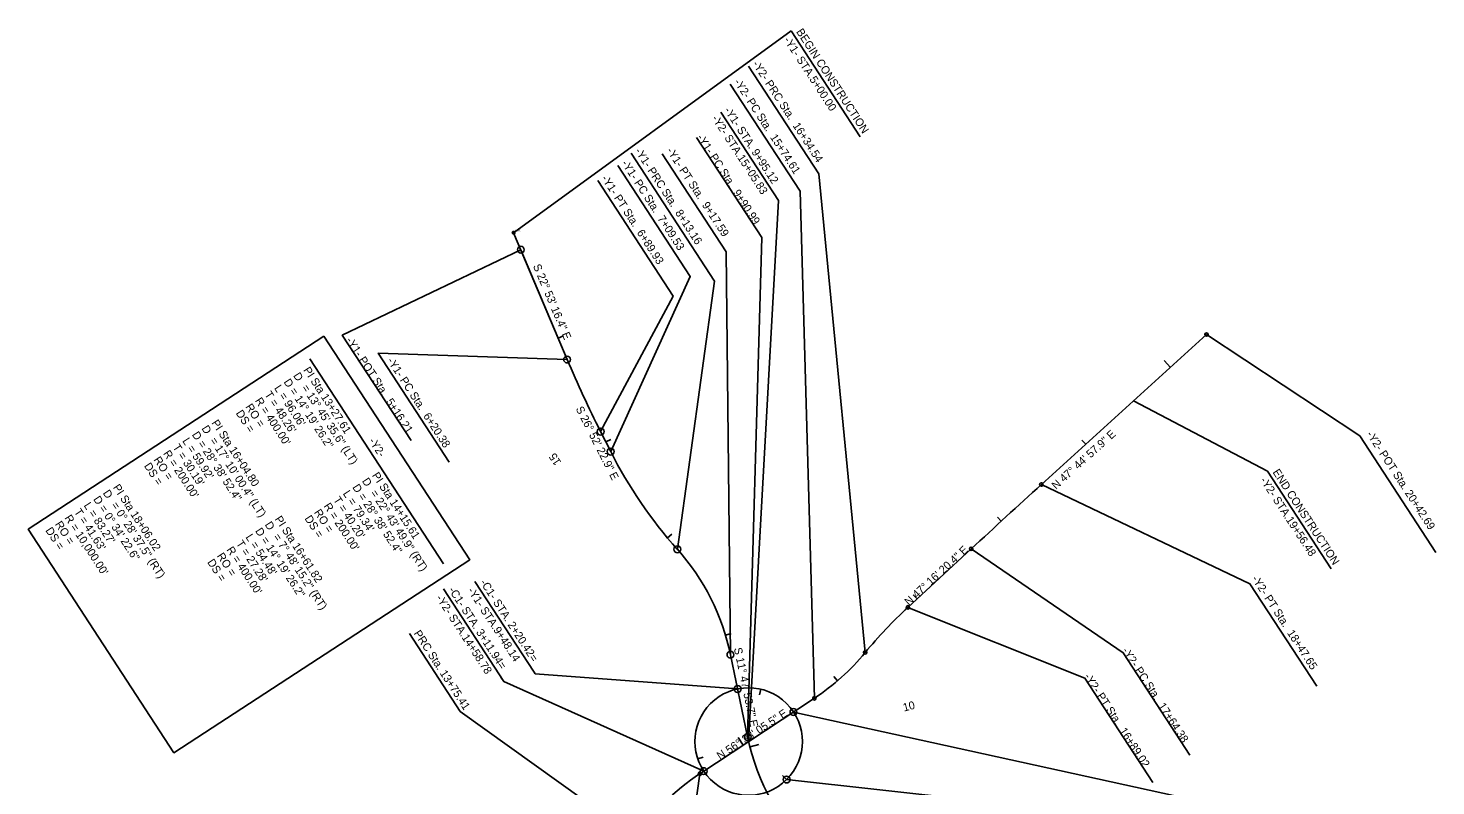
# Model space of a CAD drawing. Extents: x 1636713 to 1642783, y 841520 to 844371.
# Drawn here: x 1639748 to 1640979, y 843708 to 844371 of the extents above; entities that cross this region are included whole.
import ezdxf

# ---------------------------------------------------------------- set-up
doc = ezdxf.new("R2010")
doc.units = 0
for name, color, linetype in [('COGO Default Chain', 7, 'Continuous'), ('Cogo Default Point CELL', 7, 'Continuous'), ('COGO Default Point Number', 7, 'Continuous'), ('Prop Horizontal Alignment', 7, 'Continuous'), ('Prop Horizontal Alignment Curve and Spiral Data', 7, 'Continuous'), ('Prop Horizontal Alignment Direction Label', 7, 'Continuous'), ('Prop Horizontal Alignment Station Label', 7, 'Continuous'), ('Prop Horizontal Alignment Tick Label', 7, 'Continuous'), ('Prop Horizontal Alignment Tick Large', 7, 'Continuous'), ('Prop Horizontal Alignment Tick Small', 7, 'Continuous')]:
    doc.layers.add(name, color=color, linetype=linetype)

msp = doc.modelspace()

# ---------------------------------------------------------------- linework, layer by layer
at = {"layer": 'COGO Default Chain'}
for p, q in [((1640178.6, 844176.8), (1640219.1, 844080.8)), ((1640248.4, 844017.8), (1640257.2, 844000.3)), ((1640361.9, 843822.7), (1640376.9, 843750.8))]:
    msp.add_line(p, q, dxfattribs=at)
for centre, radius, start, end in [((1641140.4, 844469.8), 1000, 202.8879, 206.873), ((1640614, 844181.1), 400, 206.873, 221.7163), ((1640166.2, 843781.8), 200, 11.7982, 41.7163), ((1640572.7, 843791.7), 200, 191.7982, 226.5509)]:
    msp.add_arc(centre, radius, start, end, dxfattribs=at)
at = {"layer": 'Cogo Default Point CELL'}
for points in [[(1640170.8, 844191.7), (1640172.3, 844191.7)], [(1640172.3, 844193.2), (1640172.3, 844191.7)], [(1640172.3, 844191.7), (1640173.8, 844191.7)], [(1640172.3, 844191.7), (1640172.3, 844190.2)]]:
    msp.add_lwpolyline(points, dxfattribs=at)
msp.add_circle((1640172.3, 844191.7), 1.17, dxfattribs=at)
at = {"layer": 'Prop Horizontal Alignment'}
for p, q in [((1640172.3, 844191.7), (1640219.1, 844080.8)), ((1640633.8, 843971.5), (1640778.2, 844102.6)), ((1640248.4, 844017.8), (1640257.2, 844000.3)), ((1640517.1, 843864.1), (1640572.4, 843915.3)), ((1640361.9, 843822.7), (1640376.9, 843750.8)), ((1640335.2, 843718.7), (1640435.3, 843784.6))]:
    msp.add_line(p, q, dxfattribs=at)
for centre, radius, start, end in [((1641140.4, 844469.8), 1000, 202.8879, 206.873), ((1640614, 844181.1), 400, 206.873, 221.7163), ((1647357.6, 836569.4), 10000, 132.25059, 132.72767), ((1640166.2, 843781.8), 200, 11.7982, 41.7163), ((1640788.5, 843570.3), 400, 132.7277, 140.5319), ((1640325.3, 843951.7), 200, 303.3651, 320.5319), ((1640377.8, 843746.8), 47, 45, 135), ((1640377.8, 843746.8), 47, 135, 225), ((1640377.8, 843746.8), 47, 315, 45), ((1640572.7, 843791.7), 200, 191.7982, 226.5509), ((1640445.2, 843551.7), 200, 123.3651, 146.0956), ((1640377.8, 843746.8), 47, 225, 315)]:
    msp.add_arc(centre, radius, start, end, dxfattribs=at)
at = {"layer": 'Prop Horizontal Alignment Curve and Spiral Data'}
msp.add_line((1639994.1, 844081.5), (1640111.1, 843902.1), dxfattribs=at)
msp.add_lwpolyline([(1640006.3, 844101.1), (1640133.9, 843905.7), (1639875.3, 843737), (1639747.8, 843932.4)], close=True, dxfattribs=at)
at = {"layer": 'Prop Horizontal Alignment Station Label'}
for p, q in [((1640475.4, 844275.6), (1640415, 844368.2)), ((1640404, 844219.9), (1640353.5, 844297.2)), ((1640887.3, 843897.7), (1640831.5, 843983.1)), ((1640190.2, 843807.5), (1640138.5, 843886.8)), ((1640163.7, 843799.2), (1640110.9, 843880.3)), ((1640125.5, 843773.2), (1640081.1, 843841.3)), ((1640279.2, 843663.2), (1640125.5, 843773.2))]:
    msp.add_line(p, q, dxfattribs=at)
for points in [[(1640415, 844368.2), (1640172.3, 844191.7)], [(1640377.8, 844337.4), (1640439.3, 844243.2), (1640479.7, 843824.6)], [(1640361.7, 844321.6), (1640422.9, 844227.9), (1640435.3, 843784.6)], [(1640332.3, 844275), (1640389.3, 844187.6), (1640376.9, 843750.8)], [(1640275.1, 844261.2), (1640348.1, 844149.3), (1640315.5, 843914.9)], [(1640361.9, 843822.7), (1640358.1, 844175), (1640302.2, 844260.7)], [(1640263.4, 844250.5), (1640326.8, 844153.4), (1640257.2, 844000.3)], [(1640245.8, 844237.3), (1640311.7, 844136.2), (1640248.4, 844017.8)], [(1640404, 844219.9), (1640377.8, 843746.8)], [(1640082.6, 844010), (1640022.5, 844102.1), (1640178.6, 844176.8)], [(1640978.7, 843912), (1640912.2, 844014), (1640778.2, 844102.6)], [(1640219.1, 844080.8), (1640053.9, 844086.4), (1640116, 843991.2)], [(1640831.5, 843983.1), (1640714.4, 844044.7)], [(1640874.6, 843795.2), (1640816.2, 843884.7), (1640633.8, 843971.5)], [(1640763.7, 843734.9), (1640705.4, 843824.4), (1640572.4, 843915.3)], [(1640731.3, 843710.9), (1640671.9, 843802.1), (1640517.1, 843864.1)], [(1640161.2, 843803.1), (1640163.7, 843799.2), (1640338.5, 843720.9)], [(1640190.2, 843807.5), (1640191.2, 843806.1), (1640368.2, 843792.8)], [(1640761.4, 843696.8), (1640761.4, 843696.9), (1640417, 843772.6)], [(1640339.8, 843246.6), (1640281.4, 843336.1), (1640335.2, 843718.7)], [(1640737.4, 843677.4), (1640411, 843713.6)]]:
    msp.add_lwpolyline(points, dxfattribs=at)
for centre, radius in [((1640178.6, 844176.8), 3), ((1640778.2, 844102.6), 1.5), ((1640219.1, 844080.8), 3), ((1640248.4, 844017.8), 3), ((1640257.2, 844000.3), 3), ((1640633.8, 843971.5), 1.5), ((1640315.5, 843914.9), 3), ((1640572.4, 843915.3), 1.5), ((1640517.1, 843864.1), 1.5), ((1640361.9, 843822.7), 3), ((1640479.7, 843824.6), 1.5), ((1640368.2, 843792.8), 3), ((1640435.3, 843784.6), 1.5), ((1640417, 843772.6), 3), ((1640376.9, 843750.8), 3), ((1640338.5, 843720.9), 3), ((1640335.2, 843718.7), 1.5), ((1640411, 843713.6), 3)]:
    msp.add_circle(centre, radius, dxfattribs=at)
at = {"layer": 'Prop Horizontal Alignment Tick Large'}
for p, q in [((1640746.6, 844073.9), (1640741.2, 844079.9)), ((1640373, 843743.6), (1640368.6, 843750.3)), ((1640379, 843742.1), (1640386.7, 843744.1))]:
    msp.add_line(p, q, dxfattribs=at)
at = {"layer": 'Prop Horizontal Alignment Tick Small'}
for p, q in [((1640211.2, 844099.6), (1640215.8, 844101.6)), ((1640252.9, 844008.8), (1640257.4, 844011)), ((1640672.6, 844006.7), (1640669.2, 844010.4)), ((1640598.6, 843939.4), (1640595.3, 843943.1)), ((1640306.9, 843924.9), (1640310.7, 843928.1)), ((1640525.1, 843871.6), (1640521.7, 843875.2)), ((1640357.6, 843839.7), (1640362.4, 843841.2)), ((1640455.5, 843799.9), (1640452.3, 843803.7)), ((1640388.4, 843792.6), (1640387.3, 843787.7)), ((1640333.3, 843731.6), (1640338, 843733.2)), ((1640411, 843713.6), (1640407.5, 843717.1))]:
    msp.add_line(p, q, dxfattribs=at)

# ---------------------------------------------------------------- texts
at = {"layer": 'COGO Default Point Number'}
msp.add_text('15053', height=1.25, dxfattribs=at).set_placement((1640173.5, 844193))
at = {"layer": 'Prop Horizontal Alignment Curve and Spiral Data'}
for s, p in [('D', (1639979.3, 844066.7)), ('PI Sta 13+27.61', (1639988.1, 844071.6)), ("L = 96.06'", (1639962.6, 844055.8)), ('D = 14%%d 19\' 26.2"', (1639970.9, 844061.2)), ('= 13%%d 45\' 35.6" (LT)', (1639986.6, 844056.1)), ("R = 400.00'", (1639945.8, 844044.8)), ("T = 48.26'", (1639954.2, 844050.3)), ('DS =', (1639929.1, 844033.9)), ('RO = ', (1639937.4, 844039.4)), ('D = 28%%d 38\' 52.4"', (1639890.7, 844015.1)), ('D', (1639899.1, 844020.5)), ('PI Sta 16+04.80', (1639907.8, 844025.4)), ("T = 30.19'", (1639873.9, 844004.2)), ("L = 59.92'", (1639882.3, 844009.6)), ('= 17%%d 10\' 00.4" (LT)', (1639906.3, 844009.9)), ('-Y2-', (1640045.3, 844009.6)), ('RO = ', (1639857.2, 843993.2)), ("R = 200.00'", (1639865.6, 843998.7)), ('DS =', (1639848.8, 843987.8)), ('PI Sta 14+15.61', (1640048.2, 843979.5)), ('PI Sta 18+06.02', (1639821.6, 843969)), ('D = 28%%d 38\' 52.4"', (1640031, 843969.1)), ('D', (1640039.4, 843974.6)), ('D = 0%%d 34\' 22.6"', (1639804.4, 843958.7)), ('D', (1639812.8, 843964.1)), ("T = 40.20'", (1640014.3, 843958.2)), ("L = 79.34'", (1640022.7, 843963.6)), ('= 22%%d 43\' 49.9" (RT)', (1640046.7, 843964)), ("R = 10,000.00'", (1639779.3, 843942.3)), ("T = 41.63'", (1639787.7, 843947.7)), ("L = 83.27'", (1639796.1, 843953.2)), ('= 0%%d 28\' 37.5" (RT)', (1639820.1, 843953.5)), ('PI Sta 16+61.82', (1639963.1, 843941.3)), ('DS =', (1639989.2, 843941.8)), ('RO = ', (1639997.5, 843947.2)), ("R = 200.00'", (1640005.9, 843952.7)), ('DS =', (1639762.6, 843931.4)), ('RO = ', (1639770.9, 843936.8)), ('D = 14%%d 19\' 26.2"', (1639946, 843930.9)), ('D', (1639954.4, 843936.4)), ("T = 27.28'", (1639929.3, 843920)), ("L = 54.48'", (1639937.6, 843925.5)), ('= 7%%d 48\' 15.2" (RT)', (1639961.7, 843925.8)), ('RO = ', (1639912.5, 843909.1)), ("R = 400.00'", (1639920.9, 843914.5)), ('DS =', (1639904.1, 843903.6))]:
    msp.add_text(s, height=7, rotation=303.1259, dxfattribs=at).set_placement(p)
at = {"layer": 'Prop Horizontal Alignment Direction Label'}
for s, rotation, p in [('S 22%%d 53\' 16.4" E', 292.8879, (1640189.1, 844162.6)), ('S 26%%d 52\' 22.9" E', 296.873, (1640226.4, 844037.8)), ('N 47%%d 44\' 57.9" E', 42.2506, (1640646.6, 843966.8)), ('N 47%%d 16\' 20.4" E', 42.7277, (1640518, 843865.2)), ('S 11%%d 47\' 53.7" E', 281.7982, (1640364.9, 843828.3)), ('N 56%%d 38\' 05.5" E', 33.3651, (1640352.8, 843730.6))]:
    msp.add_text(s, height=7, rotation=rotation, dxfattribs=at).set_placement(p)
at = {"layer": 'Prop Horizontal Alignment Station Label'}
for s, p in [('BEGIN CONSTRUCTION', (1640419.1, 844367.4)), ('-Y1- STA.5+00.00', (1640408.2, 844360.2)), ('-Y2- PRC Sta.  16+34.54', (1640380.8, 844339.3)), ('-Y2- PC Sta.  15+74.61', (1640364.7, 844323.5)), ('-Y2- STA.15+05.83', (1640345.2, 844291.7)), ('-Y1- STA. 9+95.12', (1640356.1, 844298.8)), ('-Y1- PRC Sta.  8+13.16', (1640278, 844263.1)), ('-Y1- PT Sta.  9+17.59', (1640305.7, 844263.4)), ('-Y1- PC Sta.  9+90.99', (1640332.3, 844275)), ('-Y1- PC Sta.  7+09.53', (1640266.3, 844252.4)), ('-Y1- PT Sta.  6+89.93', (1640248.7, 844239.2)), ('-Y1- POT Sta.  5+16.21', (1640025.4, 844097.6)), ('-Y1- PC Sta.  6+20.38', (1640061.4, 844079.8)), ('-Y2- POT Sta. 20+42.69', (1640917.8, 844015.5)), ('END CONSTRUCTION', (1640835.7, 843982.3)), ('-Y2- STA.19+56.48', (1640824.8, 843975.2)), ('-C1- STA. 2+20.42=', (1640142.6, 843885.9)), ('-Y2- PT Sta.  18+47.65', (1640817.4, 843889.2)), ('-Y2- STA.14+58.78', (1640104.1, 843872.3)), ('-C1- STA. 3+11.94=', (1640115, 843879.4)), ('-Y1- STA.9+48.14', (1640131.7, 843878.8)), ('PRC Sta. 13+75.41', (1640084.7, 843841.4)), ('-Y2- PC Sta.  17+64.38', (1640704.1, 843826.3)), ('-Y2- PT Sta.  16+89.02', (1640670.8, 843803.7))]:
    msp.add_text(s, height=7, rotation=303.1259, dxfattribs=at).set_placement(p)
at = {"layer": 'Prop Horizontal Alignment Tick Label'}
for s, rotation, p in [('15', 123.3651, (1640214.2, 843991.1)), ('10', 14.3786, (1640513.7, 843773))]:
    msp.add_text(s, height=7, rotation=rotation, dxfattribs=at).set_placement(p)

doc.saveas('drawing.dxf')
